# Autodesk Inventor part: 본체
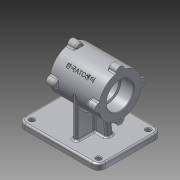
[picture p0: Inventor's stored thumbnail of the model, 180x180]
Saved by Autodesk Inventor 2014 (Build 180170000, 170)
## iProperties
Created: 2015-12
Part Number: 본체
Material: 알루미늄 6061
Document SubType Name: Modeling
Designer: basic
Density: 2.71 g/cm^3
Appearance: 알루미늄 - 평지
Mass: 1166.01 g
Surface Area: 816.021 cm^2
Volume: 430.263 cm^3
Author: basic
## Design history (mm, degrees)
sketch "스케치4"
  geometry: C1 r 37 at (0, 0); 1 further point
  constraints: 1 centre point, 1 coincident
  dimensions: "d14" = 74 diameter of C1
extrude "돌출3" new body sketch "스케치4" stored distance "d15" = 85; taper "d16" = 0 deg
sketch "스케치5"
  geometry: C1 r 7 at (0, 37); 2 further points
  constraints: 3 vertical alignment, 1 centre point, 2 other
  dimensions: "d17" = 14 diameter of C1
extrude "돌출4" join sketch "스케치5" distance "d18" = 15; taper "d19" = 0 deg
hole "구멍1" diameter "d22" = 3.242; stored, may be unused: countersink angle "d26" = 90 deg, drill point angle "d28" = 118 deg; dims "d20" = 10, "d21" = 10, "d23" = 9, "d24" = 4, "d25" = 2, "d27" = 11
node "작업 평면1"
sketch "스케치6"
  geometry: L1 (-55, 60)-(55, 60); L2 (55, 60)-(55, -80); L3 (55, -80)-(-55, -80); L4 (-55, -80)-(-55, 60); 2 further points
  constraints: 8 end point, 2 parallel, 1 horizontal, 1 midpoint, 1 perpendicular, 1 vertical alignment
  dimensions: "d33" = 110 distance of L1.start L1.end; "d34" = 140 distance of L3.end L1.start; "d35" = 80 distance from line of point (0, 0) L3
extrude "돌출5" join sketch "스케치6" distance "d36" = 10; taper "d37" = 0 deg
fillet "모깎기2" dims "d38" = 12
sketch "스케치7"
  geometry: L1 (-43, -80)-(43, -80) reference; L2 (-37, -4)-(37, -4); L3 (37, -4)-(37, 4); L4 (37, 4)-(-37, 4); L5 (-37, 4)-(-37, -4); 3 further points
  constraints: 8 end point, 2 midpoint, 2 parallel, 1 horizontal, 1 perpendicular, 1 vertical alignment
  dimensions: "d39" = 8 distance of L4.end L2.start; "d40" = 80 distance from line of L1 point (-37, 0); "d41" = 74 distance of L2.start L2.end
extrude "돌출6" join sketch "스케치7" stored distance "d42" = 10; taper "d43" = 0 deg
sketch "스케치8"
  geometry: L1 (-25, -70)-(-16.405, 0); L2 (25, -70)-(16.405, 0); L3 (48, -70)-(-68, -70) reference; L4 (-16.405, 0)-(16.405, 0); L5 (-25, -70)-(25, -70); 2 further points
  constraints: 8 end point, 2 midpoint, 1 coincident, 1 collinear, 1 horizontal, 1 parallel
  dimensions: "d44" = 97 deg angle of L3 L1; "d45" = 97 deg angle of L3 L2; "d46" = 50 distance of L2.start L1.start
extrude "돌출7" join sketch "스케치8" stored distance "d47" = 12; taper "d48" = 0 deg
fillet "모깎기3" dims "d49" = 3
fillet "모깎기4" dims "d50" = 3
hole "구멍2" diameter "d53" = 8; stored, may be unused: countersink angle "d57" = 90 deg, drill point angle "d59" = 118 deg; dims "d51" = 10, "d52" = 10, "d54" = 8, "d55" = 4, "d56" = 2, "d58" = 11
hole "구멍3" diameter "d62" = 8; stored, may be unused: countersink angle "d66" = 90 deg, drill point angle "d68" = 118 deg; dims "d60" = 10, "d61" = 10, "d63" = 8, "d64" = 4, "d65" = 2, "d67" = 11
hole "구멍4" diameter "d71" = 8; stored, may be unused: countersink angle "d75" = 90 deg, drill point angle "d77" = 118 deg; dims "d69" = 10, "d70" = 10, "d72" = 8, "d73" = 4, "d74" = 2, "d76" = 11
hole "구멍5" diameter "d80" = 8; stored, may be unused: countersink angle "d84" = 90 deg, drill point angle "d86" = 118 deg; dims "d78" = 10, "d79" = 10, "d81" = 8, "d82" = 4, "d83" = 2, "d85" = 11
fillet "모깎기5" dims "d87" = 3
chamfer "모따기1" distance "d88" = 1; stored, may be unused: second distance "d89" = 2, angle "d90" = 45 deg
fillet "모깎기6" dims "d91" = 3
hole "구멍6" diameter "d97" = 42; stored, may be unused: countersink angle "d101" = 90 deg, drill point angle "d103" = 118 deg; dims "d95" = 10, "d96" = 10, "d98" = 8, "d99" = 47, "d100" = 22, "d102" = 11
hole "구멍7" diameter "d106" = 47; stored, may be unused: countersink angle "d110" = 90 deg, drill point angle "d112" = 118 deg; dims "d104" = 10, "d105" = 10, "d107" = 8, "d108" = 47, "d109" = 22, "d111" = 22
chamfer "모따기2" distance "d113" = 1; stored, may be unused: second distance "d114" = 2, angle "d115" = 45 deg
fillet "모깎기7" dims "d116" = 0.3
node "작업 평면5"
  node "작업 평면4"
sketch "스케치10"
  geometry: 2 further points
  constraints: 1 coincident, 1 other
feature "엠보싱2" sketch "스케치10" dims "d32" = -80, "d124" = 0.5, "d125" = 0
node "솔리드2"
pattern_circular "원형 패턴1" dims angle "d30" = 360 deg
mirror "대칭1"
pattern_circular "원형 패턴2" dims angle "d93" = 360 deg
mirror "대칭2"
node "작업축2"
other parameters: "d122" = 45 deg, "d123" = 74
